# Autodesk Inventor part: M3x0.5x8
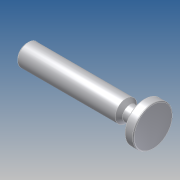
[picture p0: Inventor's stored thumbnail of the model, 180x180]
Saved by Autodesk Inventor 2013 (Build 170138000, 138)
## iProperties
Company: 한국ATC센터
Created: 2009-02
Part Number: M3x0.5x8
Document SubType Name: Modeling
Designer: KYOUNG IL JANG
Density: 7.86 g/cm^3
Mass: 68.0563 g
Surface Area: 34.7349 cm^2
Volume: 8.65856 cm^3
Material: 강, 연강
Vendor: CBT Solutions
Author: KYOUNG IL JANG
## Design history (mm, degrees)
sketch "스케치1"
  geometry: L1 (-35, 0)-(35, 0); L2 (35, 0)-(35, 11); L3 (35, 11)-(30, 11); L4 (30, 11)-(30, 4); L5 (30, 4)-(22, 4); L6 (22, 4)-(20, 6); L7 (20, 6)-(-35, 6); L8 (-35, 6)-(-35, 0); 1 further point
  constraints: 16 end point, 4 parallel, 2 midpoint, 2 perpendicular, 1 horizontal
  dimensions: "d0" = 70 distance of L1.start L1.end; "d1" = 12 diameter of L7 L1; "d2" = 22 diameter of L3 L1; "d3" = 5 distance of L2.end L3.end; "d4" = 8 diameter of L5 L1; "d5" = 135 deg angle of L6 L5; "d6" = 15 distance from line of L2 L6.end
revolve "회전1" sketch "스케치1" stored, may be unused: angle "d7" = 90 deg
chamfer "모따기1" distance "d8" = 1; stored, may be unused: second distance "d9" = 2, angle "d10" = 45 deg
fillet "모깎기1" dims "d11" = 0.5
node "솔리드1"
